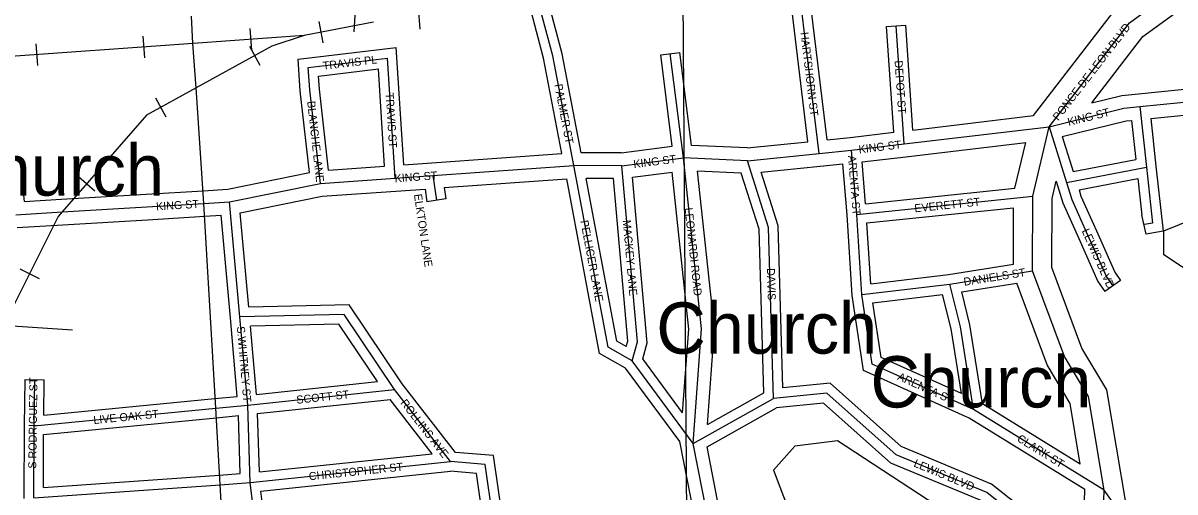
# Model space of a CAD drawing. Extents: x 418523 to 616617, y 1878279 to 2196743.
# Drawn here: x 550208 to 553806, y 2019294 to 2020757 of the extents above; entities that cross this region are included whole.
import ezdxf

# ---------------------------------------------------------------- set-up
doc = ezdxf.new("R2010")
doc.units = 0
for name, color, linetype in [('Level 1', 7, 'Continuous'), ('Level 13', 7, 'Continuous'), ('Level 14', 7, 'Continuous'), ('Level 22', 7, 'Continuous'), ('Level 23', 7, 'Continuous'), ('Level 31', 7, 'Continuous'), ('Level 32', 7, 'Continuous'), ('Level 34', 7, 'Continuous'), ('Level 37', 7, 'Continuous'), ('Level 5', 7, 'Continuous'), ('Level 57', 7, 'Continuous'), ('Level 8', 7, 'Continuous')]:
    doc.layers.add(name, color=color, linetype=linetype)

msp = doc.modelspace()

# ---------------------------------------------------------------- linework, layer by layer
at = {"layer": 'Level 1'}
for p, q in [((552242.944, 2024561.628), (552312.246, 2014734.776)), ((550362.165, 2019798.188), (544903.836, 2020159.573))]:
    msp.add_line(p, q, dxfattribs=at)
at = {"layer": 'Level 13'}
for p, q in [((553362.176, 2020217.006), (553412.855, 2020433.606)), ((553361.521, 2019983.536), (553362.176, 2020217.006))]:
    msp.add_line(p, q, dxfattribs=at)
for points in [[(553412.855, 2020433.606), (553663.797, 2020758.016), (553867.345, 2020906.547)], [(553584.925, 2019299.226), (553535.671, 2019591.384), (553460.915, 2019716.33), (553361.521, 2019983.536)], [(553575.356, 2018824.31), (553575.87, 2019007.593), (553584.925, 2019299.226)]]:
    msp.add_lwpolyline(points, dxfattribs=at)
at = {"layer": 'Level 14'}
for p, q in [((553306.257, 2020241.375), (553339.766, 2020384.596)), ((553422.16, 2020209.996), (553434.703, 2020263.609)), ((553301.58, 2020004.381), (553302.074, 2020180.619)), ((553421.554, 2019994.252), (553422.159, 2020209.996))]:
    msp.add_line(p, q, dxfattribs=at)
for points in [[(553363.613, 2020468.011), (553621.549, 2020801.465), (553831.976, 2020955.016)], [(553545.914, 2020507.553), (553706.045, 2020714.567), (553902.713, 2020858.078)], [(553653.21, 2019255.124), (553592.96, 2019612.496), (553515.231, 2019742.411), (553421.555, 2019994.252)], [(553510.392, 2019380.406), (553478.383, 2019570.271), (553406.598, 2019690.25), (553311.749, 2019945.243)], [(553515.74, 2018961.839), (553515.87, 2019008.61), (553524.949, 2019300.95)]]:
    msp.add_lwpolyline(points, dxfattribs=at)
at = {"layer": 'Level 22'}
for p, q in [((553696.023, 2020496.088), (553913.161, 2020518.028)), ((552960.483, 2020379.604), (553412.855, 2020433.606)), ((552694.202, 2020349.809), (552795.639, 2020360.068)), ((552795.639, 2020360.068), (552960.483, 2020379.604)), ((552078.669, 2020311.916), (552270.465, 2020336.464)), ((552470.405, 2020327.532), (552270.465, 2020336.464)), ((552470.405, 2020327.532), (552694.202, 2020349.809)), ((551487.873, 2020280.874), (551928.775, 2020312.344)), ((552078.669, 2020311.916), (551928.775, 2020312.344)), ((550852.879, 2020198.691), (551136.674, 2020256.425)), ((551136.674, 2020256.425), (551369.96, 2020272.484)), ((551369.96, 2020272.484), (551487.873, 2020280.874)), ((550329.897, 2020167.472), (550594.874, 2020183.071)), ((550594.874, 2020183.071), (550773.005, 2020193.83)), ((550773.005, 2020193.83), (550852.879, 2020198.691)), ((550185.997, 2020158.797), (550329.897, 2020167.472)), ((552383.694, 2019027.323), (552301.529, 2019444.676))]:
    msp.add_line(p, q, dxfattribs=at)
for points in [[(553412.855, 2020433.606), (553646.572, 2020491.136), (553696.023, 2020496.088)], [(552301.529, 2019444.676), (552327.262, 2019802.811), (552270.465, 2020336.464)]]:
    msp.add_lwpolyline(points, dxfattribs=at)
at = {"layer": 'Level 23'}
for p, q in [((553692.002, 2020535.886), (553909.14, 2020557.826)), ((552987.574, 2020423.121), (553363.612, 2020468.011)), ((553730.234, 2020459.34), (553917.183, 2020478.23)), ((552719.273, 2020392.548), (552791.614, 2020399.866)), ((552791.614, 2020399.866), (552927.919, 2020416.024)), ((552076.176, 2020351.924), (552235.715, 2020372.342)), ((552469.312, 2020367.621), (552295.809, 2020375.371)), ((552469.312, 2020367.621), (552659.56, 2020386.558)), ((552965.225, 2020339.885), (553339.766, 2020384.596)), ((551485.025, 2020320.773), (551891.016, 2020349.751)), ((552076.177, 2020351.923), (551951.635, 2020352.278)), ((552828.69, 2020323.703), (552965.191, 2020339.881)), ((550847.651, 2020238.446), (551102.679, 2020290.329)), ((551162.165, 2020298.275), (551337.48, 2020310.343)), ((551397.336, 2020314.533), (551485.034, 2020320.773)), ((552111.969, 2020275.851), (552235.014, 2020291.599)), ((552451.38, 2020288.341), (552315.166, 2020294.425)), ((552513.302, 2020291.602), (552698.165, 2020310.004)), ((552698.228, 2020310.011), (552769.02, 2020317.17)), ((551523.823, 2020243.336), (551906.105, 2020270.622)), ((552052.074, 2020271.991), (551966.859, 2020272.233)), ((550327.546, 2020207.404), (550592.523, 2020223.002)), ((550592.462, 2020222.998), (550770.594, 2020233.757)), ((550770.575, 2020233.756), (550847.651, 2020238.446)), ((550886.095, 2020164.627), (551142.059, 2020216.699)), ((551142.059, 2020216.699), (551372.708, 2020232.577)), ((551372.8, 2020232.584), (551463.794, 2020239.057)), ((550212.073, 2020200.442), (550327.49, 2020207.401)), ((550332.305, 2020127.543), (550597.225, 2020143.138)), ((550597.286, 2020143.142), (550775.418, 2020153.901)), ((550775.436, 2020153.902), (550826.54, 2020157.012)), ((550189.3, 2020118.921), (550332.305, 2020127.543)), ((552337.87, 2019052.997), (552259.495, 2019451.103)), ((552423.354, 2019032.96), (552344.337, 2019434.321))]:
    msp.add_line(p, q, dxfattribs=at)
for points in [[(553545.914, 2020507.553), (553639.765, 2020530.656), (553692.036, 2020535.89)], [(553454.032, 2020402.546), (553653.38, 2020451.617), (553670.531, 2020453.333)], [(552268.29, 2019540.218), (552287.109, 2019802.121), (552235.014, 2020291.598)], [(552345.898, 2019504.026), (552367.415, 2019803.499), (552315.166, 2020294.425)]]:
    msp.add_lwpolyline(points, dxfattribs=at)
at = {"layer": 'Level 31'}
for p, q in [((552694.202, 2020349.809), (552630.726, 2020876.935)), ((552960.483, 2020379.604), (552935.22, 2020748.428)), ((551099.049, 2020618.013), (551345.998, 2020647.488)), ((551369.96, 2020272.484), (551345.998, 2020647.488)), ((552270.465, 2020336.464), (552229.556, 2020661.694)), ((551103.919, 2020548.176), (551099.049, 2020618.013)), ((551136.674, 2020256.425), (551103.919, 2020548.176)), ((553696.023, 2020496.088), (553716.727, 2020307.29)), ((553412.855, 2020433.606), (553467.506, 2020259.258)), ((552811.87, 2020160.007), (552795.639, 2020360.068)), ((553467.506, 2020259.258), (553716.727, 2020307.29)), ((551487.873, 2020280.874), (551499.378, 2020203.953)), ((552811.87, 2020160.007), (553362.176, 2020217.006)), ((550885.44, 2019840.026), (550852.879, 2020198.691)), ((552827.961, 2019909.763), (552811.87, 2020160.007)), ((553103.128, 2019942.443), (553361.521, 2019983.536)), ((552827.961, 2019909.763), (553103.128, 2019942.443)), ((550909.685, 2019565.028), (550885.44, 2019840.026)), ((552301.529, 2019444.676), (552110.532, 2019703.42)), ((550242.402, 2019500.041), (550244.405, 2019644.409)), ((550909.685, 2019565.028), (551368.077, 2019613.897)), ((551542.683, 2019388.29), (551368.077, 2019613.897)), ((552301.529, 2019444.676), (552551.969, 2019585.431)), ((550242.402, 2019500.041), (550809.83, 2019555.133)), ((550809.83, 2019555.133), (550909.685, 2019565.028)), ((550917.23, 2019323.171), (550909.685, 2019565.028)), ((553584.925, 2019299.226), (553177.133, 2019550.571)), ((550241.751, 2019274.936), (550242.402, 2019500.041)), ((550917.23, 2019323.171), (551542.683, 2019388.29)), ((551651.042, 2019379.616), (551542.683, 2019388.29)), ((551700.139, 2019037.633), (551651.042, 2019379.616)), ((550241.751, 2019274.936), (550823.721, 2019316.166)), ((550823.721, 2019316.166), (550917.23, 2019323.171)), ((550958.105, 2018989.575), (550917.23, 2019323.171))]:
    msp.add_line(p, q, dxfattribs=at)
for points in [[(551928.775, 2020312.344), (551862.882, 2020654.375), (551823.689, 2020801.769)], [(552551.969, 2019585.431), (552536.681, 2020118.966), (552470.405, 2020327.532)], [(552110.532, 2019703.42), (552035.545, 2019745.454), (551928.775, 2020312.344)], [(552110.532, 2019703.42), (552127.178, 2019761.921), (552078.669, 2020311.916)], [(553716.727, 2020307.29), (553735.886, 2020132.316), (553710.839, 2020128.021)], [(553467.506, 2020259.258), (553484.155, 2020206.481), (553533.284, 2020096.517)], [(553533.284, 2020096.517), (553591.86, 2019965.071), (553611.429, 2019936.651)], [(553177.133, 2019550.571), (553136.027, 2019808.886), (553103.128, 2019942.443)], [(553177.133, 2019550.571), (552860.625, 2019692.928), (552827.961, 2019909.763)], [(551368.077, 2019613.897), (551210.608, 2019847.456), (550885.44, 2019840.026)], [(553575.356, 2018824.31), (553495.487, 2018935.087), (553452, 2019023.216), (553393.732, 2019152.116), (553217.921, 2019291.892), (552934.933, 2019409.426), (552718.709, 2019601.687), (552551.969, 2019585.431)], [(553783.545, 2018815.362), (553742.401, 2018948.577), (553709.616, 2019124.318), (553584.925, 2019299.226)]]:
    msp.add_lwpolyline(points, dxfattribs=at)
at = {"layer": 'Level 32'}
for p, q in [((552659.56, 2020386.558), (552600.941, 2020873.347)), ((552719.273, 2020392.548), (552660.511, 2020880.521)), ((552905.29, 2020746.378), (552965.15, 2020750.478)), ((552927.919, 2020416.024), (552905.29, 2020746.378)), ((552987.574, 2020423.121), (552965.15, 2020750.478)), ((551067.134, 2020644.416), (551373.917, 2020681.033)), ((551397.336, 2020314.533), (551373.917, 2020681.033)), ((552199.79, 2020657.949), (552259.323, 2020665.438)), ((552235.715, 2020372.342), (552199.79, 2020657.949)), ((552295.809, 2020375.371), (552259.323, 2020665.438)), ((551074.035, 2020545.457), (551067.135, 2020644.416)), ((551130.965, 2020591.607), (551318.08, 2020613.941)), ((551337.48, 2020310.343), (551318.08, 2020613.941)), ((551133.803, 2020550.893), (551130.964, 2020591.607)), ((551102.679, 2020290.329), (551074.035, 2020545.457)), ((551162.165, 2020298.274), (551133.803, 2020550.893)), ((553670.532, 2020453.334), (553683.891, 2020331.514)), ((553730.234, 2020459.34), (553746.55, 2020310.56)), ((553454.032, 2020402.546), (553488.125, 2020293.784)), ((550212.073, 2020200.442), (550199.467, 2020329.464)), ((552839.293, 2020193.008), (552828.69, 2020323.702)), ((553488.125, 2020293.784), (553683.891, 2020331.514)), ((552781.932, 2020158.082), (552769.02, 2020317.17)), ((553434.703, 2020263.609), (553438.88, 2020250.285)), ((553506.248, 2020236.171), (553690.448, 2020271.671)), ((553690.448, 2020271.671), (553702.99, 2020157.114)), ((551463.793, 2020239.057), (551469.707, 2020199.516)), ((551523.823, 2020243.336), (551529.048, 2020208.39)), ((552839.293, 2020193.008), (553306.257, 2020241.375)), ((551529.048, 2020208.39), (551469.707, 2020199.516)), ((552843.661, 2020133.138), (553302.073, 2020180.619)), ((550855.563, 2019837.313), (550826.54, 2020157.012)), ((550912.783, 2019870.659), (550886.095, 2020164.627)), ((552798.105, 2019906.559), (552781.932, 2020158.082)), ((553715.909, 2020098.452), (553702.99, 2020157.114)), ((552855.869, 2019943.288), (552843.661, 2020133.138)), ((553099.002, 2019972.164), (553301.58, 2020004.381)), ((552855.869, 2019943.288), (553099.001, 2019972.164)), ((553140.061, 2019917.938), (553311.749, 2019945.242)), ((553636.139, 2019953.664), (553586.72, 2019919.636)), ((552862.239, 2019883.621), (553080.34, 2019909.525)), ((550877.195, 2019591.955), (550855.556, 2019837.391)), ((550936.887, 2019598.098), (550918.137, 2019810.765)), ((552259.495, 2019451.104), (552090.231, 2019680.406)), ((552268.29, 2019540.219), (552143.42, 2019709.381)), ((550212.405, 2019500.457), (550214.408, 2019644.825)), ((550214.408, 2019644.825), (550274.403, 2019643.993)), ((550272.866, 2019533.141), (550274.403, 2019643.993)), ((550936.888, 2019598.098), (551315.345, 2019638.446)), ((551558.294, 2019417.136), (551392.404, 2019631.481)), ((552345.899, 2019504.026), (552521.462, 2019602.698)), ((550272.866, 2019533.141), (550806.932, 2019584.993)), ((550806.932, 2019584.993), (550877.195, 2019591.955)), ((550940.54, 2019538.145), (551354.604, 2019582.288)), ((551485.974, 2019412.547), (551354.604, 2019582.288)), ((553510.392, 2019380.406), (553204.598, 2019568.885)), ((550812.79, 2019525.278), (550880.701, 2019532.007)), ((550886.35, 2019350.941), (550880.701, 2019532.007)), ((550946.211, 2019356.349), (550940.54, 2019538.145)), ((552344.337, 2019434.321), (552561.165, 2019556.183)), ((550211.746, 2019273.237), (550212.405, 2019500.457)), ((550272.325, 2019472.804), (550812.73, 2019525.272)), ((553524.95, 2019300.95), (553163.051, 2019524.009)), ((550271.845, 2019307.143), (550272.325, 2019472.805)), ((550946.211, 2019356.35), (551485.973, 2019412.547)), ((551677.332, 2019407.607), (551558.294, 2019417.136)), ((551729.978, 2019040.907), (551677.332, 2019407.607)), ((550821.48, 2019346.083), (550886.35, 2019350.941)), ((550950.725, 2019296.494), (551543.044, 2019358.163)), ((551624.754, 2019351.622), (551543.044, 2019358.163)), ((551665.835, 2019065.475), (551624.754, 2019351.622)), ((550271.846, 2019307.144), (550821.601, 2019346.092)), ((550984.438, 2019021.343), (550950.725, 2019296.494))]:
    msp.add_line(p, q, dxfattribs=at)
for points in [[(551891.016, 2020349.751), (551833.62, 2020647.674), (551794.696, 2020794.061)], [(551951.635, 2020352.279), (551892.143, 2020661.075), (551852.682, 2020809.478)], [(552521.462, 2019602.698), (552506.813, 2020113.896), (552451.381, 2020288.341)], [(552581.038, 2019618.406), (552566.55, 2020124.036), (552513.302, 2020291.602)], [(553746.55, 2020310.556), (553768.781, 2020107.517), (553715.909, 2020098.452)], [(552090.23, 2019680.406), (552008.655, 2019726.134), (551906.105, 2020270.623)], [(552092.071, 2019748.16), (552062.434, 2019764.774), (551966.859, 2020272.233)], [(552092.071, 2019748.16), (552096.806, 2019764.803), (552052.074, 2020271.991)], [(552143.421, 2019709.381), (552157.55, 2019759.039), (552111.968, 2020275.851)], [(553438.895, 2020250.234), (553456.061, 2020195.815), (553505.892, 2020084.28)], [(553506.247, 2020236.171), (553512.247, 2020217.147), (553560.675, 2020108.755)], [(553560.686, 2020108.729), (553618.137, 2019979.807), (553636.139, 2019953.664)], [(553505.88, 2020084.306), (553565.582, 2019950.334), (553586.72, 2019919.636)], [(553163.05, 2019524.009), (552833.396, 2019672.279), (552798.105, 2019906.56)], [(553138.775, 2019600.718), (553106.596, 2019802.931), (553080.34, 2019909.525)], [(553204.598, 2019568.884), (553165.457, 2019814.842), (553140.062, 2019917.938)], [(551392.404, 2019631.481), (551226.316, 2019877.824), (550912.784, 2019870.659)], [(553138.775, 2019600.718), (552887.854, 2019713.577), (552862.239, 2019883.621)], [(551315.345, 2019638.446), (551194.9, 2019817.089), (550918.137, 2019810.765)], [(553515.74, 2018961.839), (553479.128, 2019036.036), (553418.081, 2019171.084), (553233.305, 2019317.988), (552951.099, 2019435.197), (552728.846, 2019632.819), (552581.038, 2019618.406)], [(553520.271, 2018849.415), (553469.69, 2018919.57), (553424.872, 2019010.396), (553369.382, 2019133.147), (553202.537, 2019265.796), (552918.767, 2019383.654), (552708.572, 2019570.556), (552561.165, 2019556.183)]]:
    msp.add_lwpolyline(points, dxfattribs=at)
at = {"layer": 'Level 37'}
for p, q in [((551242.476, 2020729.819), (551246.881, 2020797.018)), ((551442.352, 2020804.707), (551447.781, 2020737.583)), ((551302.587, 2020759.621), (551085.71, 2020718.422)), ((551131.814, 2020761.454), (551144.382, 2020695.294)), ((550916.278, 2020739.865), (550921.161, 2020672.7)), ((550248.315, 2020692.044), (550253.098, 2020624.871)), ((550582.331, 2020715.821), (550587.114, 2020648.648)), ((550915.053, 2020684.95), (550947.509, 2020625.943)), ((550621.62, 2020523.673), (550654.027, 2020464.64)), ((550381.271, 2020277.696), (550432.046, 2020233.457)), ((550197.97, 2019990.459), (550258.141, 2019960.221))]:
    msp.add_line(p, q, dxfattribs=at)
for points in [[(551085.71, 2020718.422), (550739.265, 2020693.236), (550125.621, 2020649.553), (548242.201, 2020514.691), (548150.914, 2020508.051), (547641.895, 2020375.731), (547458.405, 2020267.905), (547214.096, 2020063.162), (546823.005, 2019735.215), (546101.487, 2019130.063), (545879.085, 2018943.447), (545642.385, 2018744.875), (544473.775, 2017765.446), (540869.835, 2014744.684)], [(551085.71, 2020718.422), (550985.474, 2020685.254), (550748.692, 2020555.017), (550593.165, 2020469.641), (550329.897, 2020167.472), (550317.497, 2020153.326), (550124.977, 2019770.219), (550111.681, 2019665.886), (550090.929, 2019503.39), (550081.8, 2019086.659), (550112.939, 2018567.259), (550277.4, 2015818.589), (550313.99, 2015209.351), (550337.57, 2014813.981), (550343.335, 2014719.061)]]:
    msp.add_lwpolyline(points, dxfattribs=at)
at = {"layer": 'Level 5'}
msp.add_lwpolyline([(553937.237, 2019924.446), (553770.861, 2020033.346), (553771.09, 2020108.368), (553913.012, 2020166.261)], dxfattribs=at)
msp.add_lwpolyline([(553224.035, 2018501.214), (553324.306, 2018567.587), (553408.812, 2018925.786), (553342.578, 2019067.699), (552751.937, 2019453.101), (552618.525, 2019436.848), (552551.574, 2019362.056), (552634.25, 2019145.012), (552641.894, 2018936.607), (552683.545, 2018928.107), (552875.508, 2018994.171), (553017.062, 2018943.702), (553125.017, 2018818.331), (553158.07, 2018718.158), (553149.57, 2018676.507), (553224.035, 2018501.214)], close=True, dxfattribs=at)
at = {"layer": 'Level 8'}
msp.add_lwpolyline([(550837.849, 2019063.609), (550823.845, 2019316.614), (550809.84, 2019555.62), (550772.828, 2020193.634), (550748.82, 2020554.642), (550738.818, 2020693.646), (550733.816, 2020778.647)], dxfattribs=at)

# ---------------------------------------------------------------- texts
at = {"layer": 'Level 34'}
for s, height, rotation, p in [('PONCE DE LEON BLVD', 25, 52.275803, (553441.546, 2020450.275)), ('HARTSHORN ST', 25, 276.865358, (552636.16, 2020727.266)), ('TRAVIS PL', 25, 6.80575, (551145.662, 2020610.99)), ('DEPOT ST', 25, 273.917497, (552930.15, 2020639.52)), ('TRAVIS ST', 25, 273.655156, (551340.415, 2020538.869)), ('PALMER ST', 25, 280.903531, (551867.467, 2020564.5)), ('BLANCHE LANE', 25, 276.404792, (551095.384, 2020512.176)), ('KING ST', 25, 13.827808, (553473.981, 2020435.781)), ('KING ST', 24.9992, 6.757928, (552819.482, 2020350.307)), ('KING ST', 25, 7.292717, (552116.17, 2020304.116)), ('ARENTA ST', 25, 274.637408, (552784.497, 2020342.847)), ('KING ST', 25, 4.069378, (551369.483, 2020259.92)), ('ELKTON LANE', 25, 278.506022, (551428.808, 2020221.953)), ('KING ST', 25, 3.455936, (550624.329, 2020172.328)), ('LEONARDI ROAD', 25, 276.074203, (552274.584, 2020179.655)), ('EVERETT ST', 25, 5.912669, (552993.385, 2020166.244)), ('PELLICER LANE', 25, 280.665294, (551948.629, 2020139.406)), ('MACKEY LANE', 24.99916, 275.039361, (552081.135, 2020141.701)), ('LEWIS BLVD', 25, 294.018172, (553514.233, 2020108.561)), ('DAVIS', 25, 271.640206, (552531.466, 2019991.981)), ('DANIELS ST', 25, 9.035686, (553147.97, 2019936.919)), ('S.WHITNEY ST', 25, 275.037519, (550875.583, 2019809.515)), ('S RODRIGUEZ ST', 25, 89.204519, (550249.215, 2019366.393)), ('ARENTA ST', 25, 335.78225, (552937.057, 2019644.846)), ('SCOTT ST', 25, 6.084583, (551063.161, 2019568.821)), ('ROLLINS AVE', 24.99916, 307.736881, (551385.356, 2019571.151)), ('LIVE OAK ST', 25, 5.544814, (550429.046, 2019505.606)), ('CLARK ST', 25, 328.35135, (553310.524, 2019453.673)), ('LEWIS BLVD', 25, 337.444708, (552987.861, 2019373.909)), ('CHRISTOPHER ST', 25, 5.943236, (551102.027, 2019329.845))]:
    msp.add_text(s, height=height, rotation=rotation, dxfattribs=at).set_placement(p)
at = {"layer": 'Level 57'}
for p in [(549958.632, 2020218.369), (552185.94, 2019725.221), (552854.93, 2019557.367)]:
    msp.add_text('Church', height=160, dxfattribs=at).set_placement(p)

doc.saveas('drawing.dxf')
